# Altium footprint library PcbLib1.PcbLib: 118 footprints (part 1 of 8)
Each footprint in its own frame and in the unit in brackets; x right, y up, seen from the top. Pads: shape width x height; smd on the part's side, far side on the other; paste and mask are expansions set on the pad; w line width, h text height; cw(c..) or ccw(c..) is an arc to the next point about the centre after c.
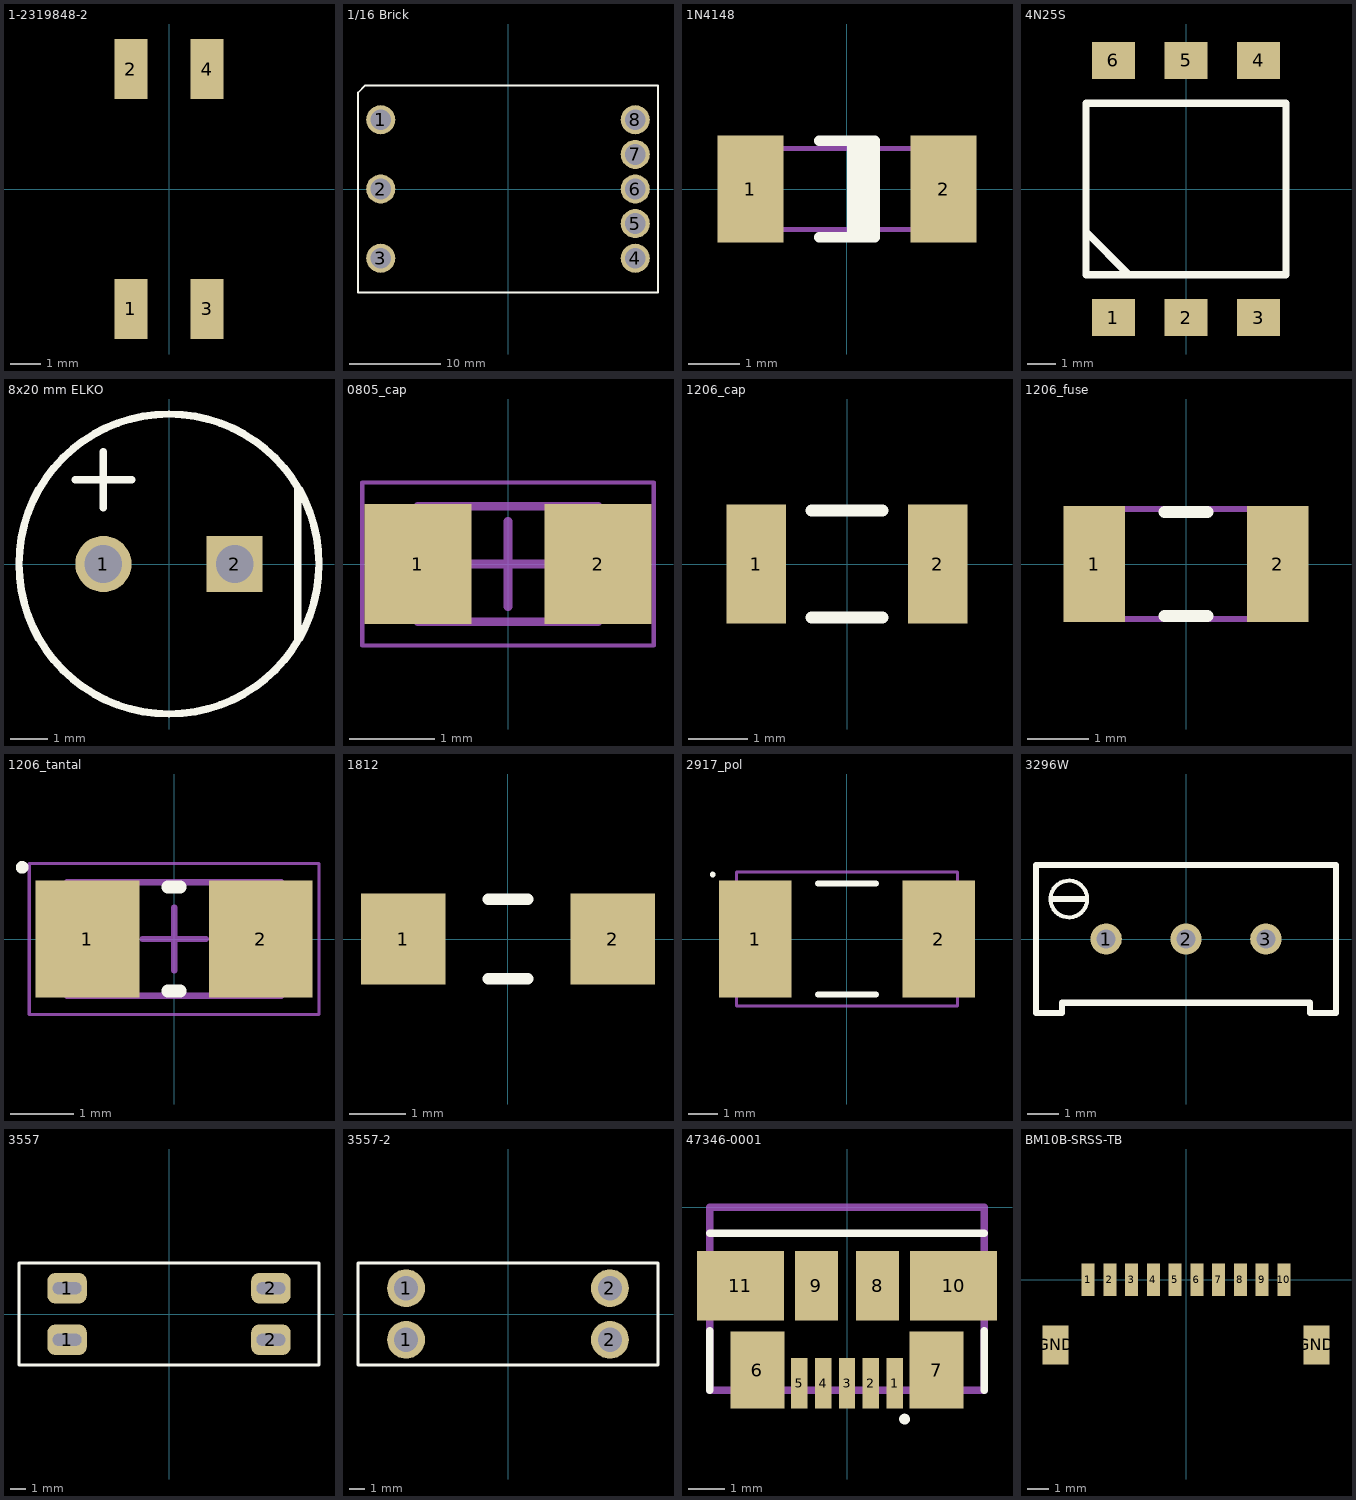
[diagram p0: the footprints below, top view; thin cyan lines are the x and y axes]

## 1-2319848-2 [mm]
pads (4):
  rect 1.1x2 smd mask+0.03: 1(-1.27,-4) 2(-1.27,4) 3(1.27,-4) 4(1.27,4)
3D body "1-2319848-2.STEP": height 3.44, standoff -0.01, extent -2.49,-3.93 2.49,3.93

## 1/16 Brick [mm] "V36SE12004NRFA"
pads (8):
  round 3.2 hole 2.3: 1(-14,7.62) 2(-14,0) 3(-14,-7.62) 4(14,-7.62) 5(14,-3.81) 6(14,0) 7(14,3.81) 8(14,7.62)
Top Overlay:
  lines w0.2: -16.5,-11.4 -16.5,10.6 -15.7,11.4 16.5,11.4 16.5,-11.4 -16.5,-11.4

## 1N4148 [mm] "QuadroMELF (SOD-80)"
height 1.6
pads (2):
  rect 1.3x2.1 smd: 1(-1.9,0) 2(1.9,0)
Top Overlay:
  rectangle: 0,-0.95 0.55,0.95
  lines w0.2: -0.55,-0.95 0.55,-0.95 0.55,0.95 -0.55,0.95
Mechanical 13:
  lines w0.1: -1.85,-0.8 1.85,-0.8 1.85,0.8 -1.85,0.8 -1.85,-0.8
3D body "SOD-80.step": height 1.5, standoff 0.01, extent -1.75,-0.749 1.75,0.749

## 4N25S [mm] "SMD"
pads (6):
  rect 1.5x1.3 smd: 1(-2.54,-4.5) 2(0,-4.5) 3(2.54,-4.5) 4(2.54,4.5) 5(0,4.5) 6(-2.54,4.5)
Top Overlay:
  lines w0.254: -3.5,-1.5 -2,-3 -2.5,-3 ; -3.5,-3 -3.5,3 3.5,3 3.5,-3 -3.5,-3

## 8x20 mm ELKO [mm]
pads (2):
  round 1.5 hole 1: 1(-1.75,0)
  rect 1.5x1.5 hole 1: 2(1.75,0)
Top Overlay:
  circle w0.2: c0,0 r4
  lines w0.2: -2.5,2.25 -1,2.25 ; -1.75,1.5 -1.75,3 ; 3.429,-2.032 3.429,2.032
3D body "8x20_radial.STEP": height 20, standoff -3, extent -4,-4 4,3.999

## 0805_cap [mm]
height 0.95
pads (2):
  rect 1.25x1.4 smd mask+0.035: 1(-1.05,0) 2(1.05,0)
Mechanical 13:
  lines w0.1: -1.05,-0.675 1.05,-0.675 1.05,0.675 -1.05,0.675 -1.05,-0.675
Mechanical 15:
  lines w0.05: -1.7,-0.95 1.7,-0.95 1.7,0.95 -1.7,0.95 -1.7,-0.95
  lines w0.1: -0.5,0 0.5,0 ; 0,-0.5 0,0.5
3D body "0805_cap.step": height 0.95, standoff 0, extent -1.05,-0.675 1.05,0.675

## 1206_cap [mm]
height 0.9
pads (2):
  rect 1x2 smd: 1(-1.525,0) 2(1.525,0)
Top Overlay:
  lines w0.2: -0.6,-0.9 0.6,-0.9 ; -0.6,0.9 0.6,0.9
3D body "1206_cap.step": height 0.9, standoff 0, extent -1.675,-0.875 1.675,0.875

## 1206_fuse [mm] "Bell fuse"
height 0.85
pads (2):
  rect 1x1.9 smd: 1(-1.5,0) 2(1.5,0)
Top Overlay:
  lines w0.2: -0.35,-0.85 0.35,-0.85 ; -0.35,0.85 0.35,0.85
Mechanical 13:
  lines w0.1: -1.75,-0.9 1.75,-0.9 1.75,0.9 -1.75,0.9 -1.75,-0.9
3D body "1206_fuse.step": height 0.85, standoff 0, extent -1.75,-0.9 1.75,0.9

## 1206_tantal [mm] "3216-18 AVX"
height 1.8
pads (2):
  rect 1.65x1.85 smd: 1(-1.375,0) 2(1.375,0)
Top Overlay:
  circle w0.1: c-2.412,1.137 r0.05
  lines w0.2: -0.1,-0.825 0.1,-0.825 ; -0.1,0.825 0.1,0.825
Mechanical 13:
  lines w0.1: -1.7,-0.9 1.7,-0.9 1.7,0.9 -1.7,0.9 -1.7,-0.9
Mechanical 15:
  lines w0.05: -2.3,-1.2 2.3,-1.2 2.3,1.2 -2.3,1.2 -2.3,-1.2
  lines w0.1: -0.5,0 0.5,0 ; 0,-0.5 0,0.5
3D body "1206_tantal.step": height 1.8, standoff 0, extent -1.7,-0.9 1.7,0.9

## 1812 [mm] "1812 size inductor"
height 3.4
pads (2):
  rect 1.5x1.6 smd: 1(-1.85,0) 2(1.85,0)
Top Overlay:
  lines w0.2: -0.35,-0.7 0.35,-0.7 ; -0.35,0.7 0.35,0.7
3D body "1812.step": height 3.4, standoff 0, extent -2.4,-1.7 2.4,1.7

## 2917_pol [mm] "Vishay tantalum"
height 3.1
pads (2):
  rect 2.5x4 smd: 1(-3.15,0) 2(3.15,0)
Top Overlay:
  circle w0.1: c-4.612,2.212 r0.05
  lines w0.2: -1,-1.9 1,-1.9 ; -1,1.9 1,1.9
Mechanical 13:
  lines w0.1: -3.8,-2.3 3.8,-2.3 3.8,2.3 -3.8,2.3 -3.8,-2.3
3D body "2917_pol.step": height 3.1, standoff 0, extent -3.8,-2.3 3.8,2.3

## 3296W [mm] "Bourns 3296W"
pads (3):
  round 1 hole 0.6: 1(-2.54,0) 2(0,0) 3(2.54,0)
Top Overlay:
  circle w0.127: c-3.72,1.27 r0.583
  lines w0.2: -4.22,1.27 -3.22,1.27 ; -4.765,-2.35 -4.765,2.35 4.765,2.35 4.765,-2.35 3.937,-2.35 3.937,-2.029 -3.937,-2.029 -3.937,-2.35 -4.765,-2.35
3D body "bourns_3296_pot.STEP": height 11.55, standoff -2.5, extent -4.765,-2.41 4.765,2.421

## 3557 [mm] "Keystone fuse holder w fuse"
pads (4):
  rrect50% 2.6x2 hole 0.8 slot 1.9 at 0 deg: 1(-6.731,-1.702) 1(-6.731,1.702) 2(6.731,-1.702) 2(6.731,1.702)
Top Overlay:
  lines w0.2: -9.906,-3.365 9.906,-3.365 9.906,3.365 -9.906,3.365 -9.906,-3.365
3D body "keystone-PN3557-2.x_t": height 7.41, standoff -2.75, extent -9.961,-3.337 9.851,3.394

## 3557-2 [mm] "Keystone fuse holder w fuse"
pads (4):
  round 2.5 hole 1.6: 1(-6.731,-1.702) 1(-6.731,1.702) 2(6.731,-1.702) 2(6.731,1.702)
Top Overlay:
  lines w0.2: -9.906,-3.365 -9.906,3.365 9.906,3.365 9.906,-3.365 -9.906,-3.365
3D body "keystone-PN3557-2.STEP": height 7.41, standoff -2.75, extent -9.906,-3.366 9.906,3.365

## 47346-0001 [mm]
pads (11):
  rect 0.45x1.38 smd: 1(1.3,-4.81) 2(0.65,-4.81) 3(0,-4.81) 4(-0.65,-4.81) 5(-1.3,-4.81)
  rect 1.475x2.1 smd: 6(-2.452,-4.45) 7(2.452,-4.45)
  rect 1.175x1.9 smd: 8(0.837,-2.15) 9(-0.837,-2.15)
  rect 2.375x1.9 smd: 10(2.913,-2.15) 11(-2.913,-2.15)
Top Overlay:
  circle w0.2: c1.572,-5.79 r0.046
  lines w0.2: -3.75,-5 -3.75,-3.373 ; -3.75,-0.709 3.75,-0.709 ; 3.75,-5 3.75,-3.373
Mechanical 15:
  lines w0.2: -3.75,-5 3.75,-5 3.75,0 -3.75,0 -3.75,-5
3D body "473461001.stp": height 2.7, standoff -0.01, extent -3.9,-4.936 3.9,0.064

## BM10B-SRSS-TB [mm] "1mm pitch JST-SH"
pads (12):
  rect 0.6x1.5 smd: 1(-4.5,0) 2(-3.5,0) 3(-2.5,0) 4(-1.5,0) 5(-0.5,0) 6(0.5,0) 7(1.5,0) 8(2.5,0) 9(3.5,0) 10(4.5,0)
  rect 1.2x1.8 smd: GND(-6,-3) GND(6,-3)
3D body "BM10B-SRSS-TB.STEP": height 4.31, standoff -0.01, extent -6.05,-3.55 5.95,0.05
